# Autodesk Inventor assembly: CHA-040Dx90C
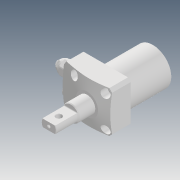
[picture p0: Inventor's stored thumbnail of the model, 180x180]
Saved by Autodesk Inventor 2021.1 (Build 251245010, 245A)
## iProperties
Created: 2019-12
Part Number: CHA-040Dx90C
Description: STEP AP203
Document SubType Name: Assembly
Designer: user
Title: CHA-040Dx90C.STEP
Revision Number: ÈÎºÎ
Sending System: SolidWorks 2017
Preprocessor: SwSTEP 2.0
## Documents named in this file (5)
- D:\Vault_2016\Projekty\Clamptek\Hydraulic\CHA\CHA\CHA-040\Inventor\CHA-040Dx90C\CHA-040Dx90C.iam
- D:\Vault_2016\Projekty\Clamptek\Hydraulic\CHA\CHA\CHA-040\Inventor\CHA-040Dx90C\CHA-040±¾Ìå.ipt
- D:\Vault_2016\Projekty\Clamptek\Hydraulic\CHA\CHA\CHA-040\Inventor\CHA-040Dx90C\CHA-040D(Ë«±Û£©»îÈû¸Ë.ipt
- D:\Vault_2016\Projekty\Clamptek\Hydraulic\CHA\CHA\CHA-040\Inventor\CHA-040Dx90C\G1-8¶ÂÍ·.ipt
- D:\Vault_2016\Projekty\Clamptek\Hydraulic\CHA\CHA\CHA-040\Inventor\CHA-040Dx90C\CZL10µ÷ËÙ·§.ipt
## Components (4 placed, 4 different names)
1. CHA-040±¾Ìå_1
2. CHA-040D(Ë«±Û£©»îÈû¸Ë_2
3. G1-8¶ÂÍ·_3
4. CZL10µ÷ËÙ·§_4
